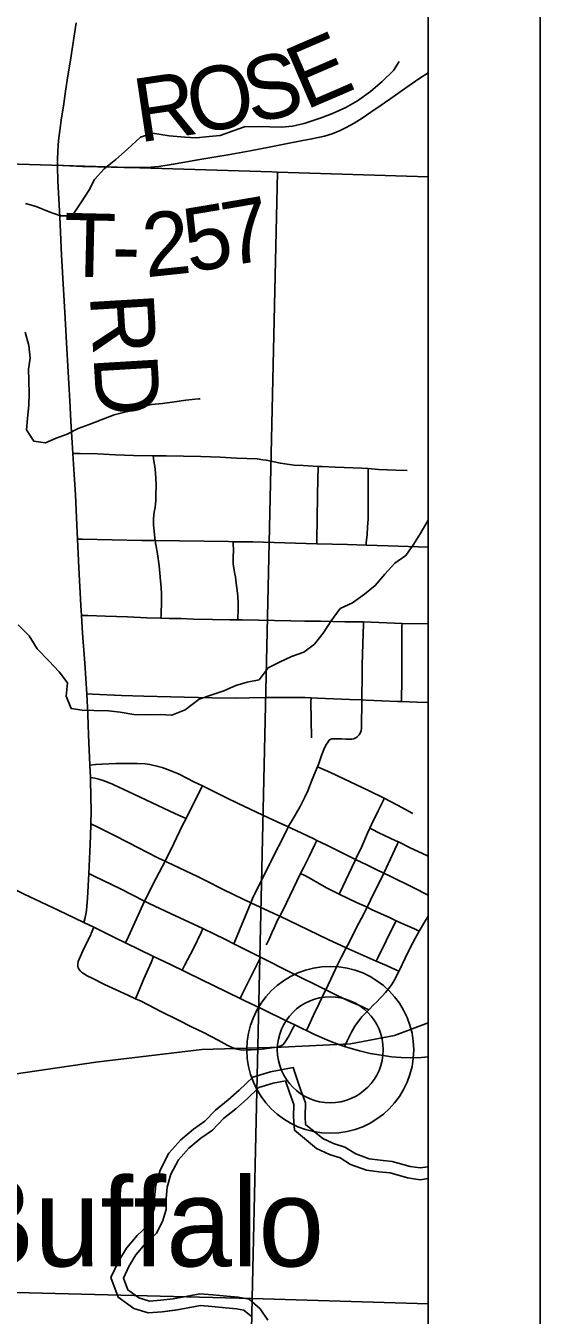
# Model space of a CAD drawing. Extents: x 0 to 34, y 0 to 22.
# Drawn here: x 29.958 to 30.417, y 19.567 to 20.718 of the extents above; entities that cross this region are included whole.
import ezdxf

# ---------------------------------------------------------------- set-up
doc = ezdxf.new("R2010")
doc.units = 0
for name, color, linetype in [('GM_X_Corporation', 7, 'Continuous'), ('GM_X_County_Road', 7, 'Continuous'), ('GM_X_County_Road_Text', 7, 'Continuous'), ('GM_X_Major_River', 7, 'Continuous'), ('GM_X_Minor_River', 7, 'Continuous'), ('GM_X_Rail_Line', 7, 'Continuous'), ('GM_X_State_Route', 7, 'Continuous'), ('GM_X_Township_Road', 7, 'Continuous'), ('GM_X_Township_Road_Text', 7, 'Continuous'), ('GM_X_Unincorporated', 7, 'Continuous'), ('GM_X_Unincorporated_Location', 7, 'Continuous'), ('GM_X_Unincorporated_Text', 7, 'Continuous'), ('SH_Data', 7, 'Continuous')]:
    doc.layers.add(name, color=color, linetype=linetype)

msp = doc.modelspace()

# ---------------------------------------------------------------- linework, layer by layer
at = {"layer": 'GM_X_Corporation'}
for points in [[(26.6535, 14.621), (27.01, 14.6164), (27.046, 14.6155), (27.043, 14.755), (27.052, 15.403), (27.0676, 16.5549), (27.0694, 16.6556), (27.0775, 16.888), (27.0944, 18.0731), (27.1039, 18.5696), (27.1064, 18.6537), (27.3971, 18.6436), (28.3421, 18.6121), (28.7772, 18.6028), (29.0074, 18.5935), (29.6561, 18.5791), (29.6772, 18.5786), (30.101, 18.5701), (30.3167, 18.565), (30.3167, 20.9), (23.5167, 20.9)], [(26.3378, 16.673), (27.0694, 16.6556), (27.0775, 16.888), (27.0944, 18.0731), (27.1039, 18.5696), (27.1064, 18.6537), (27.3971, 18.6436), (28.3421, 18.6121), (28.7772, 18.6028), (29.0074, 18.5935), (29.6561, 18.5791), (29.6772, 18.5786), (30.101, 18.5701), (30.3167, 18.565), (30.3167, 20.9), (25.1014, 20.9)]]:
    msp.add_lwpolyline(points, dxfattribs=at)
for points in [[(29.1631, 20.6187), (29.6667, 20.6028), (30.1775, 20.5873), (30.1824, 20.5872), (30.1599, 19.5824), (29.1414, 19.6082)], [(30.3167, 19.5775), (30.3167, 20.5828), (30.1824, 20.5872), (30.1599, 19.5824)], [(30.1599, 19.5824), (30.1382, 18.5689), (29.1208, 18.5959), (29.1414, 19.6082)], [(30.3167, 18.5647), (30.3167, 19.5775), (30.1599, 19.5824), (30.1382, 18.5689)]]:
    msp.add_lwpolyline(points, close=True, dxfattribs=at)
at = {"layer": 'GM_X_County_Road'}
msp.add_line((30.0157, 20.0471), (30.0153, 20.0582), dxfattribs=at)
for points in [[(29.9862, 20.5932), (29.9863, 20.5983), (29.9866, 20.6058), (29.9873, 20.6152), (29.9883, 20.6244), (29.99, 20.6355), (29.9916, 20.6459), (29.9934, 20.6595), (29.9956, 20.673), (29.998, 20.6871), (30.0029, 20.7203)], [(30.0001, 20.3362), (29.9983, 20.365), (29.9973, 20.383), (29.9948, 20.4295), (29.9933, 20.4568), (29.99, 20.5132), (29.9883, 20.5474), (29.9867, 20.579), (29.9862, 20.5921), (29.9862, 20.5932)], [(30.0043, 20.2597), (30.0034, 20.2788), (30.0023, 20.2993), (30.0007, 20.3265), (30.0001, 20.3362)], [(30.0076, 20.1915), (30.0072, 20.2006), (30.0055, 20.2341), (30.0043, 20.2597)], [(30.0124, 20.1217), (30.0106, 20.1491), (30.0086, 20.1758), (30.0076, 20.1915)], [(30.0153, 20.0582), (30.0141, 20.0853), (30.0138, 20.094), (30.0134, 20.1033), (30.0124, 20.1217)], [(30.0162, 20.0057), (30.0163, 20.017), (30.0157, 20.0443), (30.0157, 20.0471)], [(30.0142, 19.9615), (30.0152, 19.9811), (30.0157, 19.9948), (30.0162, 20.0057)], [(30.0098, 19.9179), (30.0109, 19.9222), (30.0117, 19.9253), (30.0122, 19.9284), (30.0131, 19.9395), (30.0142, 19.9615)]]:
    msp.add_lwpolyline(points, dxfattribs=at)
at = {"layer": 'GM_X_Major_River'}
for points in [[(30.0907, 19.5719), (30.0796, 19.5706), (30.0673, 19.5695), (30.0543, 19.5736), (30.0404, 19.5835), (30.0339, 19.6011), (30.0409, 19.6159), (30.0479, 19.6273), (30.0574, 19.6387), (30.0663, 19.647), (30.0702, 19.6549), (30.0728, 19.6632), (30.0727, 19.672), (30.0739, 19.6837), (30.0778, 19.697), (30.0856, 19.7121), (30.0963, 19.7239), (30.1077, 19.7335), (30.1177, 19.7405), (30.1272, 19.7505), (30.1385, 19.7597), (30.1483, 19.7682), (30.1604, 19.7797), (30.1761, 19.7845), (30.1965, 19.7883), (30.2028, 19.7697), (30.2073, 19.757), (30.207, 19.7446), (30.2075, 19.7377), (30.2229, 19.725), (30.2324, 19.7206), (30.2425, 19.7175), (30.2523, 19.7114), (30.2642, 19.707), (30.2739, 19.7058), (30.2848, 19.7047), (30.3006, 19.7002), (30.3098, 19.6988), (30.3167, 19.6998)], [(30.3167, 19.6998), (30.3098, 19.6988), (30.3006, 19.7002), (30.2848, 19.7047), (30.2739, 19.7058), (30.2642, 19.707), (30.2523, 19.7114), (30.2425, 19.7175), (30.2324, 19.7206), (30.2229, 19.725), (30.2075, 19.7377), (30.207, 19.7446), (30.2073, 19.757), (30.2028, 19.7697), (30.1965, 19.7883), (30.1761, 19.7845), (30.1604, 19.7797), (30.1483, 19.7682), (30.1385, 19.7597), (30.1272, 19.7505), (30.1177, 19.7405), (30.1077, 19.7335), (30.0963, 19.7239), (30.0856, 19.7121), (30.0778, 19.697), (30.0739, 19.6837), (30.0727, 19.672), (30.0728, 19.6632), (30.0702, 19.6549), (30.0663, 19.647), (30.0574, 19.6387), (30.0479, 19.6273), (30.0409, 19.6159), (30.0339, 19.6011), (30.0404, 19.5835), (30.0543, 19.5736), (30.0673, 19.5695), (30.0796, 19.5706), (30.0911, 19.5719)], [(30.0896, 19.5822), (30.0786, 19.5809), (30.0684, 19.5801), (30.0589, 19.583), (30.049, 19.5901), (30.0452, 19.6006), (30.05, 19.6109), (30.0563, 19.6212), (30.0649, 19.6315), (30.0747, 19.6407), (30.0799, 19.651), (30.0832, 19.6617), (30.0831, 19.6715), (30.0842, 19.6818), (30.0875, 19.6932), (30.0942, 19.7061), (30.1035, 19.7164), (30.114, 19.7253), (30.1245, 19.7326), (30.1343, 19.7429), (30.1452, 19.7517), (30.1553, 19.7605), (30.1658, 19.7705), (30.1786, 19.7744), (30.1896, 19.7764), (30.1931, 19.7662), (30.1969, 19.7553), (30.1966, 19.7443), (30.1975, 19.7326), (30.2173, 19.7161), (30.2287, 19.7109), (30.2382, 19.708), (30.2477, 19.702), (30.2617, 19.6969), (30.2727, 19.6955), (30.2829, 19.6944), (30.2984, 19.6901), (30.3098, 19.6883), (30.3167, 19.6893)], [(30.174, 19.563), (30.1671, 19.5731), (30.1572, 19.5817), (30.1474, 19.5835), (30.1372, 19.5846), (30.1247, 19.5856), (30.1133, 19.5866), (30.1024, 19.5846), (30.0896, 19.5822)], [(30.0911, 19.5719), (30.1043, 19.5744), (30.1138, 19.5761), (30.1238, 19.5752), (30.1362, 19.5742), (30.1459, 19.5732), (30.1526, 19.572), (30.1593, 19.5662)], [(30.1593, 19.5662), (30.1526, 19.572), (30.1459, 19.5732), (30.1362, 19.5742), (30.1238, 19.5752), (30.1138, 19.5761), (30.1043, 19.5744), (30.0915, 19.572)]]:
    msp.add_lwpolyline(points, dxfattribs=at)
at = {"layer": 'GM_X_Minor_River'}
for points in [[(29.9578, 20.5592), (29.9672, 20.5566), (29.979, 20.5518), (29.9889, 20.5481), (29.9994, 20.5482), (30.0076, 20.5605), (30.0144, 20.5708), (30.0192, 20.5807), (30.0278, 20.5902), (30.0383, 20.5983), (30.0488, 20.6075), (30.0604, 20.6182), (30.071, 20.6218), (30.0858, 20.6196), (30.0998, 20.6183), (30.11, 20.6176), (30.1217, 20.6189), (30.1315, 20.6197), (30.1428, 20.624), (30.153, 20.6275), (30.1651, 20.6277), (30.1757, 20.6274), (30.1859, 20.6271), (30.1957, 20.628), (30.2062, 20.6304), (30.2213, 20.6355), (30.2315, 20.6394), (30.2435, 20.6448), (30.2537, 20.6506), (30.2653, 20.659), (30.2759, 20.6679), (30.286, 20.6778), (30.2908, 20.6858)], [(29.9576, 20.4443), (29.9608, 20.4326), (29.962, 20.4213), (29.9606, 20.4114), (29.9607, 20.4012), (29.9611, 20.3894), (29.9609, 20.3796), (29.9595, 20.3674), (29.9588, 20.3572), (29.9653, 20.347), (29.9755, 20.3456), (29.9853, 20.3499), (29.9951, 20.3534), (30.0049, 20.3584), (30.0147, 20.3619), (30.0252, 20.3662), (30.0369, 20.3705), (30.0486, 20.3737), (30.0592, 20.3776), (30.0701, 20.38), (30.0799, 20.3808), (30.0905, 20.3821), (30.1007, 20.3837), (30.112, 20.3849), (30.1135, 20.385)], [(29.9512, 20.1832), (29.9612, 20.1734), (29.9681, 20.1618), (29.9787, 20.1513), (29.9879, 20.1415), (29.9952, 20.1317), (29.9941, 20.1196), (29.9984, 20.1086), (30.0082, 20.1072), (30.0188, 20.107), (30.0317, 20.1067), (30.0423, 20.1053), (30.0544, 20.1032), (30.065, 20.1029), (30.0778, 20.1034), (30.0884, 20.1028), (30.1001, 20.1074), (30.1125, 20.117), (30.1238, 20.1209), (30.1347, 20.1245), (30.1453, 20.1291), (30.1554, 20.1323), (30.166, 20.1343), (30.1742, 20.145), (30.1844, 20.15), (30.1949, 20.155), (30.2059, 20.1589), (30.2156, 20.1662), (30.2231, 20.1758), (30.2302, 20.1868), (30.2384, 20.1979), (30.2493, 20.203), (30.2599, 20.2106), (30.2696, 20.2183), (30.2782, 20.2286), (30.2872, 20.2382), (30.297, 20.2451), (30.3037, 20.2551), (30.3097, 20.2646), (30.3156, 20.2745), (30.3167, 20.2766)]]:
    msp.add_lwpolyline(points, dxfattribs=at)
at = {"layer": 'GM_X_Rail_Line'}
msp.add_lwpolyline([(28.8515, 19.5134), (29.4007, 19.6833), (29.491, 19.707), (29.5813, 19.7244), (29.9149, 19.7778), (30.0206, 19.7932), (30.1151, 19.8044), (30.1859, 19.8065), (30.2475, 19.8096), (30.2867, 19.817), (30.3167, 19.8284)], dxfattribs=at)
at = {"layer": 'GM_X_State_Route'}
for points in [[(29.937, 19.9528), (29.9567, 19.9432), (29.9869, 19.9287), (30.0098, 19.9179), (30.0187, 19.9135)], [(30.0187, 19.9135), (30.0384, 19.9038), (30.0469, 19.8997), (30.072, 19.8876), (30.0809, 19.8833), (30.0975, 19.8752), (30.1021, 19.8729), (30.1261, 19.8613), (30.1492, 19.8501), (30.1529, 19.8483), (30.1692, 19.8404), (30.1909, 19.8298), (30.1978, 19.8265), (30.2056, 19.8227)], [(30.2056, 19.8227), (30.2083, 19.8215), (30.2156, 19.818), (30.2286, 19.8123), (30.2378, 19.8087), (30.2423, 19.8072), (30.246, 19.8059), (30.2556, 19.8032), (30.2652, 19.801), (30.2749, 19.7993), (30.2841, 19.7981), (30.2928, 19.7974), (30.3014, 19.7972), (30.3107, 19.7974), (30.3167, 19.7979)]]:
    msp.add_lwpolyline(points, dxfattribs=at)
at = {"layer": 'GM_X_Township_Road'}
for p, q in [((30.2592, 20.1859), (30.2935, 20.1845)), ((30.2935, 20.1845), (30.3167, 20.1841)), ((30.1435, 19.8988), (30.1586, 19.9354)), ((30.1435, 19.8988), (30.1673, 19.8868)), ((30.2438, 19.8953), (30.2705, 19.8834))]:
    msp.add_line(p, q, dxfattribs=at)
for points in [[(29.9862, 20.5932), (29.9918, 20.5929), (30.0085, 20.5923), (30.0222, 20.5918), (30.0458, 20.5912), (30.0588, 20.5912), (30.0662, 20.5914), (30.0767, 20.5923), (30.0895, 20.5942), (30.1048, 20.5969), (30.1097, 20.5977), (30.1293, 20.6012), (30.1385, 20.6027), (30.1581, 20.6062), (30.1751, 20.6095), (30.1885, 20.6122), (30.205, 20.6153), (30.2117, 20.6166), (30.2201, 20.6182), (30.2243, 20.6192), (30.2313, 20.6214), (30.2382, 20.6242), (30.2437, 20.6268), (30.2508, 20.6307), (30.2581, 20.6352), (30.2658, 20.6405), (30.2749, 20.6469), (30.2779, 20.649), (30.2825, 20.6523), (30.2977, 20.6628), (30.3094, 20.6709), (30.3167, 20.6758)], [(30.0001, 20.3362), (30.0064, 20.3361), (30.0219, 20.3357), (30.0381, 20.3349), (30.0542, 20.3344), (30.0715, 20.3342)], [(30.0715, 20.3342), (30.0733, 20.3342), (30.0832, 20.3341), (30.1142, 20.3334), (30.1315, 20.3328), (30.1458, 20.3321), (30.1551, 20.3318), (30.1644, 20.3313), (30.1693, 20.3306), (30.1724, 20.3302), (30.1851, 20.3275), (30.1912, 20.3265), (30.1974, 20.3258), (30.2055, 20.3253), (30.2186, 20.3246)], [(30.0734, 20.2584), (30.0731, 20.2605), (30.0723, 20.2698), (30.072, 20.2722), (30.0719, 20.274), (30.0719, 20.2783), (30.0726, 20.2838), (30.0733, 20.2881), (30.0741, 20.2943), (30.0741, 20.298), (30.0744, 20.3084), (30.0737, 20.319), (30.073, 20.3246), (30.0722, 20.3294), (30.0715, 20.3342)], [(30.2174, 20.2557), (30.2174, 20.2579), (30.2179, 20.2792), (30.2184, 20.3149), (30.2186, 20.3219), (30.2186, 20.3246)], [(30.2186, 20.3246), (30.2222, 20.3245), (30.234, 20.3241), (30.2576, 20.3231), (30.2633, 20.3227)], [(30.2614, 20.2544), (30.2616, 20.2564), (30.2623, 20.2639), (30.2627, 20.2703), (30.263, 20.2742), (30.2632, 20.2776), (30.2633, 20.2818), (30.2634, 20.2992), (30.2633, 20.3195), (30.2633, 20.3227)], [(30.2633, 20.3227), (30.2725, 20.322), (30.288, 20.3212), (30.298, 20.3209)], [(30.0043, 20.2597), (30.0086, 20.2596), (30.0616, 20.2586), (30.0734, 20.2584)], [(30.0734, 20.2584), (30.1389, 20.2575), (30.1429, 20.2574)], [(30.0786, 20.1892), (30.0789, 20.1921), (30.0788, 20.1945), (30.0792, 20.2019), (30.0791, 20.2062), (30.079, 20.2104), (30.0787, 20.217), (30.0783, 20.2225), (30.0777, 20.2294), (30.077, 20.236), (30.0755, 20.2465), (30.074, 20.255), (30.0738, 20.2556), (30.0736, 20.2568), (30.0734, 20.2584)], [(30.1472, 20.1878), (30.1475, 20.1986), (30.1475, 20.2026), (30.1472, 20.2088), (30.1466, 20.2138), (30.1453, 20.223), (30.1449, 20.2261), (30.1441, 20.2299), (30.1437, 20.2324), (30.1432, 20.2353), (30.1429, 20.2381), (30.1428, 20.2412), (30.143, 20.2453), (30.1431, 20.2485), (30.1429, 20.2574)], [(30.1429, 20.2574), (30.1606, 20.2572), (30.2174, 20.2557)], [(30.2174, 20.2557), (30.2449, 20.255), (30.2614, 20.2544)], [(30.2614, 20.2544), (30.281, 20.2538), (30.3167, 20.2526)], [(30.0076, 20.1915), (30.0135, 20.1916), (30.0291, 20.191), (30.0488, 20.1904), (30.0661, 20.1896), (30.0786, 20.1892)], [(30.0786, 20.1892), (30.0859, 20.1891), (30.0965, 20.1889), (30.1076, 20.1885), (30.1244, 20.1882), (30.1399, 20.1879), (30.1472, 20.1878)], [(30.1472, 20.1878), (30.1511, 20.1878), (30.1944, 20.1869), (30.2068, 20.1866), (30.221, 20.1865), (30.2426, 20.1861), (30.2592, 20.1859)], [(30.2578, 20.1163), (30.2578, 20.1178), (30.2581, 20.1382), (30.258, 20.1476), (30.2582, 20.1569), (30.2585, 20.1668), (30.2591, 20.1839), (30.2592, 20.1859)], [(30.2931, 20.1148), (30.2931, 20.1166), (30.2932, 20.1337), (30.2932, 20.1595), (30.2934, 20.1824), (30.2935, 20.1845)], [(30.0124, 20.1217), (30.0174, 20.1215), (30.0435, 20.1203), (30.0634, 20.1198), (30.0994, 20.1188), (30.1242, 20.1182), (30.1447, 20.118), (30.1572, 20.1181), (30.1726, 20.1185), (30.207, 20.1184), (30.2124, 20.1182)], [(30.2128, 20.0824), (30.2123, 20.1148), (30.2124, 20.1182)], [(30.2124, 20.1182), (30.2182, 20.118), (30.2324, 20.1172), (30.2467, 20.1167), (30.2578, 20.1163)], [(30.218, 20.0567), (30.2192, 20.0597), (30.2217, 20.0667), (30.2245, 20.0736), (30.2263, 20.0769), (30.2269, 20.078), (30.2278, 20.0795), (30.2285, 20.0804), (30.2299, 20.0813), (30.2309, 20.0816), (30.2323, 20.0815), (30.2357, 20.0817), (30.2395, 20.0816), (30.2434, 20.0814), (30.2457, 20.0814), (30.2475, 20.0813), (30.2487, 20.0814), (30.2505, 20.0817), (30.2522, 20.0824), (30.2532, 20.083), (30.2545, 20.0842), (30.2553, 20.0851), (30.2562, 20.0867), (30.257, 20.0889), (30.2574, 20.0913), (30.2578, 20.1163)], [(30.2578, 20.1163), (30.2616, 20.1161), (30.2894, 20.1149), (30.2931, 20.1148)], [(30.2931, 20.1148), (30.3068, 20.1143), (30.3167, 20.114)], [(30.0153, 20.0582), (30.0202, 20.0586), (30.0259, 20.0591), (30.0383, 20.0596), (30.0457, 20.0596), (30.0501, 20.0597), (30.0575, 20.0597), (30.0644, 20.0592), (30.0688, 20.0586), (30.0749, 20.0573), (30.0797, 20.0559), (30.0867, 20.0535), (30.0947, 20.05), (30.108, 20.0434), (30.1155, 20.0398)], [(30.1921, 20.003), (30.1962, 20.0099), (30.2027, 20.0213), (30.2069, 20.0295), (30.2094, 20.0351), (30.2134, 20.0454), (30.2172, 20.0545), (30.218, 20.0567)], [(30.218, 20.0567), (30.2298, 20.0517), (30.2473, 20.0434), (30.2643, 20.0353), (30.2776, 20.0287)], [(30.0157, 20.0471), (30.0195, 20.0464), (30.0232, 20.0457), (30.0279, 20.0443), (30.0331, 20.0422), (30.0348, 20.0414), (30.0365, 20.0406), (30.0404, 20.0388), (30.0505, 20.0341), (30.0544, 20.0323), (30.0916, 20.0147), (30.0962, 20.0127), (30.101, 20.0106)], [(30.101, 20.0106), (30.1135, 20.0359), (30.1155, 20.0398)], [(30.1155, 20.0398), (30.1191, 20.0379), (30.1369, 20.0291), (30.1469, 20.0243), (30.1637, 20.0162), (30.1743, 20.0111), (30.1822, 20.0075), (30.1907, 20.0037), (30.1921, 20.003)], [(30.2648, 20.0018), (30.2664, 20.0053), (30.2723, 20.0175), (30.2766, 20.0264), (30.2776, 20.0287)], [(30.2776, 20.0287), (30.2894, 20.0225), (30.303, 20.0149)], [(30.0162, 20.0057), (30.0216, 20.0031), (30.0361, 19.9961), (30.0499, 19.9889), (30.0659, 19.9806), (30.0764, 19.9752), (30.0823, 19.9724)], [(30.0823, 19.9724), (30.09, 19.9883), (30.0976, 20.0039), (30.101, 20.0106)], [(30.1586, 19.9354), (30.1603, 19.9393), (30.1627, 19.9443), (30.1727, 19.9642), (30.176, 19.9709), (30.191, 20.0007), (30.1921, 20.003)], [(30.1921, 20.003), (30.1997, 19.9995), (30.2143, 19.9926), (30.2175, 19.991)], [(30.2031, 19.9615), (30.2059, 19.9672), (30.2106, 19.9767), (30.2158, 19.9875), (30.2175, 19.991)], [(30.2175, 19.991), (30.2265, 19.9867), (30.242, 19.9789), (30.2509, 19.9745), (30.2521, 19.974)], [(30.2521, 19.974), (30.2576, 19.9855), (30.2628, 19.9974), (30.2648, 20.0018)], [(30.2648, 20.0018), (30.2672, 20.0006), (30.2723, 19.9982), (30.288, 19.9907), (30.2902, 19.9896)], [(30.2772, 19.9618), (30.2891, 19.9873), (30.2902, 19.9896)], [(30.2902, 19.9896), (30.3008, 19.9845), (30.3156, 19.9775)], [(30.0639, 19.9369), (30.0744, 19.9573), (30.0823, 19.9724)], [(30.0823, 19.9724), (30.0842, 19.9715), (30.0949, 19.9665), (30.1112, 19.9588), (30.1195, 19.9546), (30.1328, 19.9478), (30.1444, 19.9421), (30.1586, 19.9354)], [(30.2374, 19.9431), (30.2379, 19.9442), (30.2515, 19.9725), (30.2521, 19.974)], [(30.2521, 19.974), (30.2621, 19.9692), (30.2705, 19.9651), (30.2772, 19.9618)], [(30.3156, 19.9775), (30.3165, 19.9771), (30.3167, 19.977)], [(30.0142, 19.9615), (30.0191, 19.9591), (30.0425, 19.9477), (30.0639, 19.9369)], [(30.1845, 19.9233), (30.1873, 19.9286), (30.2031, 19.9615)], [(30.2031, 19.9615), (30.2068, 19.9596), (30.2107, 19.9576), (30.2262, 19.9487), (30.2345, 19.9444), (30.2374, 19.9431)], [(30.2623, 19.9314), (30.2626, 19.9321), (30.2653, 19.9376), (30.2675, 19.9421), (30.2769, 19.961), (30.2772, 19.9618)], [(30.2772, 19.9618), (30.2828, 19.959), (30.3034, 19.9489), (30.3167, 19.9422)], [(30.0469, 19.8997), (30.0495, 19.9054), (30.0639, 19.9369)], [(30.0639, 19.9369), (30.0682, 19.9347), (30.0871, 19.9257), (30.1159, 19.9124)], [(30.1586, 19.9354), (30.1792, 19.9257), (30.1845, 19.9233)], [(30.2374, 19.9431), (30.253, 19.9357), (30.2623, 19.9314)], [(30.1724, 19.8979), (30.1731, 19.8989), (30.1751, 19.9028), (30.1775, 19.9085), (30.1795, 19.9131), (30.1826, 19.9198), (30.1845, 19.9233)], [(30.1845, 19.9233), (30.1925, 19.9196), (30.2276, 19.9026), (30.2438, 19.8953)], [(30.2438, 19.8953), (30.2449, 19.8974), (30.2505, 19.9084), (30.253, 19.9134), (30.2593, 19.9254), (30.2623, 19.9314)], [(30.2623, 19.9314), (30.267, 19.9292), (30.2822, 19.9221), (30.2883, 19.9193)], [(30.3088, 19.9101), (30.3134, 19.9181), (30.3167, 19.9234)], [(30.0056, 19.876), (30.0049, 19.8773), (30.0045, 19.8786), (30.0044, 19.8797), (30.0044, 19.8807), (30.0049, 19.8831), (30.0067, 19.8877), (30.0101, 19.8952), (30.016, 19.9069), (30.0164, 19.908), (30.0187, 19.9135)], [(30.0975, 19.8752), (30.0997, 19.8794), (30.1076, 19.8947), (30.1144, 19.909), (30.1159, 19.9124)], [(30.1159, 19.9124), (30.1361, 19.9026), (30.1435, 19.8988)], [(30.2705, 19.8834), (30.2719, 19.8862), (30.2869, 19.9165), (30.2883, 19.9193)], [(30.2883, 19.9193), (30.2889, 19.919), (30.2963, 19.9157), (30.3047, 19.912), (30.3088, 19.9101)], [(30.2907, 19.8743), (30.2912, 19.8753), (30.2963, 19.8859), (30.3016, 19.8971), (30.3054, 19.9042), (30.3088, 19.9101)], [(30.056, 19.8498), (30.0577, 19.8538), (30.0634, 19.8674), (30.0697, 19.882), (30.072, 19.8876)], [(30.2083, 19.8215), (30.2104, 19.826), (30.2147, 19.8351), (30.2197, 19.8456), (30.2239, 19.8544), (30.2255, 19.8577), (30.2321, 19.8716), (30.2361, 19.88), (30.2396, 19.8872), (30.2438, 19.8953)], [(30.0056, 19.876), (30.0065, 19.8747), (30.0076, 19.8735), (30.0094, 19.8722), (30.0127, 19.8703), (30.0171, 19.868), (30.0283, 19.8626), (30.0491, 19.853), (30.056, 19.8498)], [(30.1492, 19.8501), (30.1513, 19.8545), (30.1664, 19.8849), (30.1673, 19.8868)], [(30.1673, 19.8868), (30.1956, 19.8725), (30.2245, 19.8582), (30.2255, 19.8577)], [(30.2705, 19.8834), (30.2797, 19.8793), (30.2881, 19.8755), (30.2907, 19.8743)], [(30.2638, 19.84), (30.2684, 19.8445), (30.2711, 19.8471), (30.2741, 19.8502), (30.2758, 19.852), (30.2788, 19.8552), (30.2826, 19.8601), (30.2847, 19.8632), (30.2876, 19.8681), (30.2907, 19.8743)], [(30.2255, 19.8577), (30.2345, 19.8533), (30.2469, 19.8473), (30.2525, 19.8448), (30.2571, 19.843), (30.2599, 19.8418), (30.2638, 19.84)], [(30.056, 19.8498), (30.061, 19.8475), (30.0792, 19.8381), (30.0936, 19.8309), (30.1058, 19.8248), (30.1164, 19.8196), (30.1295, 19.8127), (30.135, 19.8098), (30.1381, 19.8082), (30.1405, 19.807), (30.143, 19.806), (30.1451, 19.8051)], [(30.2423, 19.8072), (30.2446, 19.8121), (30.2452, 19.8133), (30.2484, 19.8199), (30.2515, 19.8252), (30.2546, 19.8297), (30.2577, 19.8335), (30.2638, 19.84)], [(30.1451, 19.8051), (30.1481, 19.8044), (30.1495, 19.8043), (30.1526, 19.804), (30.1556, 19.8041), (30.1589, 19.8042), (30.1689, 19.8049), (30.1775, 19.8061), (30.1821, 19.8067), (30.1834, 19.807), (30.1845, 19.8074), (30.186, 19.808), (30.1871, 19.8088), (30.1887, 19.8104), (30.1906, 19.8131), (30.193, 19.817), (30.1962, 19.8234), (30.1978, 19.8265)]]:
    msp.add_lwpolyline(points, dxfattribs=at)
at = {"layer": 'GM_X_Unincorporated'}
for radius in [0.0744, 0.0472]:
    msp.add_circle((30.2295, 19.8042), radius, dxfattribs=at)
at = {"layer": 'GM_X_Unincorporated_Location'}
msp.add_line((30.2295, 19.8042), (30.2295, 19.8042), dxfattribs=at)
at = {"layer": 'SH_Data'}
for points in [[(23.4167, 21), (30.4167, 21), (30.4167, 14), (23.4167, 14)], [(23.5167, 20.9), (30.3167, 20.9), (30.3167, 14.1), (23.5167, 14.1)]]:
    msp.add_lwpolyline(points, close=True, dxfattribs=at)

# ---------------------------------------------------------------- texts
at = {"layer": 'GM_X_County_Road_Text'}
msp.add_text('RD', height=0.05682, rotation=273.4277, dxfattribs=at).set_placement((30.0151, 20.4775))
at = {"layer": 'GM_X_Township_Road_Text'}
for s, rotation, p in [('E', 23.2946, (30.2073, 20.6422)), ('S', 13.0219, (30.1594, 20.6301)), ('O', 10.1356, (30.1071, 20.6207)), ('R', 8.4889, (30.0592, 20.6135)), ('7', 9.6835, (30.1384, 20.5032)), ('5', 9.5778, (30.1038, 20.4974)), ('T', 358.6714, (29.9914, 20.4941)), ('2', 6.0122, (30.0651, 20.4932)), ('-', 359.3418, (30.0346, 20.4931))]:
    msp.add_text(s, height=0.0568, rotation=rotation, dxfattribs=at).set_placement(p)
at = {"layer": 'GM_X_Unincorporated_Text'}
msp.add_text('Buffalo', height=0.07898, rotation=0, dxfattribs=at).set_placement((29.8953, 19.611))

doc.saveas('drawing.dxf')
